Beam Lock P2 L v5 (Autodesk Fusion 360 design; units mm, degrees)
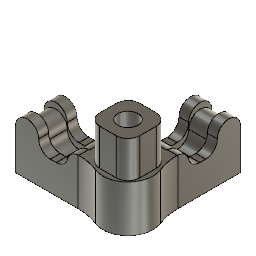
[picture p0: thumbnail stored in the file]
parameter "heatset_entry" = 5.2
parameter "heatset_depth" = 4
parameter "heatset_taperby" = 0.2
parameter "recip_thickness" = 3.2
parameter "recip_slotwidth" = 7
parameter "print_wall" = 0.435 (= "( 0.87 / 2 ) * 1 mm")
parameter "recip_distfrom" = 4.5
parameter "recip_tooth" = 1 comment "extra length to lock-in"
parameter "recip_slotdepth" = 10
sketch "Sketch1" plane through (0, 0, 0) normal (0, 0, 1) x axis (1, 0, 0)
  line L1 (-16, -1.6) -> (-12, -1.6)
  line L2 (-16, 1.6) -> (-16, -1.6)
  line L3 (-12, 1.6) -> (-16, 1.6)
  line L4 (-12, -1.6) -> (-12, 1.6)
  line L5 (0, 1.73) -> (0, 2.6)
  line L6 (0, -1.73) -> (0, -2.6)
  line L7 (0, 4.3) -> (0, 2.6)
  line L8 (0, -4.3) -> (0, -2.6)
  line L9 (-7, 1.6) -> (-12, 1.6)
  line L10 (-7, -1.6) -> (-12, -1.6)
  line L11 (-7, -1.6) -> (-7, 1.6)
  line L12 (-4, 1.6) -> (-7, 1.6)
  line L13 (-4, -1.6) -> (-4, 1.6)
  line L14 (-7, -1.6) -> (-4, -1.6)
  line L15 (-4, 3.3) -> (-4, 1.6)
  line L16 (-16, 3.3) -> (-4, 3.3)
  line L17 (-16, 1.6) -> (-16, 3.3)
  line L18 (-16, 0) -> (0, 0)
  line L19 (-12, 3.3) -> (-12, 1.6)
  line L20 (-7, 3.3) -> (-7, 1.6)
  line L21 (-2.7568, 3.3) -> (-4, 3.3)
  line L22 (3.43, -3.43) -> (-3.43, -3.43)
  line L23 (3.43, 3.43) -> (3.43, -3.43)
  line L24 (-3.43, 3.43) -> (3.43, 3.43)
  line L25 (-3.43, -3.43) -> (-3.43, 3.43)
  line L26 (3.43, 3.43) -> (-3.43, -3.43)
  line L27 (-3.43, 3.43) -> (3.43, -3.43)
  circle C1 centre (0, 0) radius 1.625
  circle C2 centre (0, 0) radius 3
  circle C3 centre (0, 0) radius 2.6
  circle C4 centre (0, 0) radius 1.73
  circle C5 centre (0, 0) radius 4.3
  point P1 (0, 0)
  point P2 (0, 0)
  point P5 (0, 0)
  point P10 (0, 2.6)
  point P11 (0, -2.6)
  point P12 (0, 1.73)
  point P13 (0, -1.73)
  point P14 (-12, 0)
  point P3 (0, 0)
  point P4 (0, 0)
  point P15 (0, 0)
  point P16 (0, 4.3)
  point P17 (0, -4.3)
  point P18 (-7, -1.6)
  point P21 (-7, -1.6)
  point P8 (-16, 1.6)
  point P24 (-16, 1.6)
  point P25 (0, 0)
  point P26 (-16, 0)
  point P27 (-12, 3.3)
  point P28 (-7, 3.3)
  point P30 (-2.7568, 3.3)
  point P35 (0, 0)
  point P36 (0, -3.43)
  point P37 (0, -1.73)
  point P7 (-16, -1.6)
  point P9 (-12, 1.6)
  point P20 (-4, -1.6)
  point P23 (-16, 3.3)
  coincident P1 P2
  concentric C1 C2
  concentric C2 C3
  coincident P1 P5
  horizontal L1
  vertical L2
  horizontal L3
  coincident C3 P10
  coincident C3 P11
  coincident C4 P12
  coincident C4 P13
  vertical L4
  midpoint L4 P14
  coincident P3 L5
  coincident P4 L6
  vertical L5
  vertical L6
  horizontal P1 P14
  coincident P1 P15
  coincident C5 P16
  vertical L7
  coincident C5 P17
  parallel L7 L8
  perpendicular L4 L9
  perpendicular L4 L10
  perpendicular L11 L12
  perpendicular L12 L13
  perpendicular L13 L14
  coincident P18 P21
  perpendicular L12 L15
  perpendicular L15 L16
  perpendicular L16 L17
  coincident P8 P24
  coincident P2 P25
  midpoint L2 P26
  coincident L16 P27
  perpendicular L16 L19
  coincident L16 P28
  perpendicular L16 L20
  vertical L20
  coincident C5 P30
  perpendicular L15 L21
  perpendicular L22 L23
  parallel L22 L24
  parallel L23 L25
  horizontal L22
  coincident L26 P35
  coincident L27 P35
  coincident P5 P35
  midpoint L22 P36
  coincident P13 P37
  equal L22 L25
  dimension "d1" diameter C1 = 3.25
  dimension "d2" diameter C2 = 6
  dimension "d3" diameter C3 = 5.2 (= "heatset_entry")
  dimension "d4" distance C3 C4 = 0.87 (= "print_wall * 2")
  dimension "d11" distance P7 P8 = 3.2 (= "recip_thickness")
  dimension "d29" distance P8 P9 = 4
  dimension "d69" distance P11 P17 = 1.7
  dimension "d70" distance L4 P18 = 5
  dimension "d71" distance P20 P21 = 3
  dimension "d72" distance P23 P24 = 1.7
  dimension "d95" distance P15 L13 = 4
  dimension "d99" distance P36 P37 = 1.7
  dimension "d104" distance P15 L22 = 3.43
extrude "Extrude7" new body sketch "Sketch1" profile of C3 C4 L2 L3 L4 L5 L6 C5 L7 L8 L9 L11 L12 L13 L14 L15 L16 L17 L18 L19 L20 L21 along normal blind 8 (= "heatset_depth + 4 mm")
extrude "Extrude9" cut sketch "Sketch1" profile of C3 C4 L5 L6 L18 along normal blind 4 (= "heatset_depth")
chamfer "Chamfer8" distance 0.2 (= "heatset_taperby") distance 4 (= "heatset_depth")
chamfer "Chamfer9" distance 0.4
extrude "Extrude8" sketch "Sketch1" profile of L4 C5 L9 L11 L16 L18 L19 L20 blind -4
extrude "Extrude10" sketch "Sketch1" profile of L9 L16 L19 L20 blind 1
extrude "Extrude11" sketch "Sketch1" profile of L3 L16 L17 L19 blind 1
fillet "Fillet12" radius 2
fillet "Fillet13" radius 2
fillet "Fillet14" radius 10
mirror "Mirror2"
combine "Combine2"
chamfer "Chamfer10" distance 0.87
copy_paste_bodies "CopyPasteBodies2"
move "Move2"
combine "Combine4"
fillet "Fillet16" radius 4
extrude "Extrude12" sketch "Sketch1" profile of C3 C4 L5 L6 C5 L7 L8 L18 L21 L22 L23 L24 L25 blind 6.25
fillet "Fillet17" radius 2
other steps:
base_feature "Base Feature"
